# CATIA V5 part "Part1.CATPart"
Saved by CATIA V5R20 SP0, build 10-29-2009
Part number: 底盖
Bounding box of the stored display mesh (mm): x -5 to 4, y -23.984 to 44.814, z -19.949 to 19.949
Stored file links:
  D:\CATIA Data\Part1.CATPart
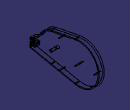
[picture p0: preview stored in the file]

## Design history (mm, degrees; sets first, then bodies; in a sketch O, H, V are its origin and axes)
Body1 (main body)
  Sketch1 on yz-plane, origin (0, 0, 0), H (0, 1, 0), V (0, 0, 1)
    arc A1 centre (0, 0) radius 15 from (-3, 14.6969) to (-12.973, 7.5301) ccw
    arc A2 centre (25, 0) radius 20 from (21, -19.5959) to (21, 19.5959) ccw
    point P1 (25, 0)
    line L1 (21, 19.5959) -> (-3, 14.6969)
    line L2 (21, -19.5959) -> (-3, -14.6969)
    arc A3 centre (-32, 18.5742) radius 22 from (-23.9842, -1.9136) to (-12.973, 7.5301) ccw
    point P6 (-32, 18.5742)
    point P7 (-12.973, 7.5301)
    line L3 (-3, -14.6969) -> (-23.9842, -10.4136)
    line L4 (-23.9842, -10.4136) -> (-23.9842, -1.9136)
    radius A1 = 15
    distance P1 V = 25
    radius A2 = 20
    radius A3 = 22
    distance P6 V = 32
    length L4 = 8.5
    coincidence: P1 H, A3 P7, P7 A1, L3 L2
    tangency: L1 A1, L1 A2, L2 A1, L2 A2, A3 A1, L3 A1
    vertical: L4 V
  Pad1: profile Sketch1, direction (1, 0, 0), length -5
  Shell1: IntOffset 1, Face start face of Pad1, ExtOffset 0
  Sketch2 on face of Shell1, origin (-4, 0, 0), H (0, 1, 0), V (0, 0, 1)
    circle A1 centre (0, 0) radius 1.5
    radius A1 = 1.5
  Pad2: profile Sketch2, direction (1, 0, 0), length 7
  Sketch3 on end face of Pad2, origin (3, 0, 0), H (0, 1, 0), V (0, 0, 1)
    point P1 (0, 0)
  Hole1: placed by Sketch3, at (3, 0, 0) direction (-1, 0, 0), diameter 2, depth 5
  Sketch4 on face of Shell1, origin (-4, 0, 0), H (0, 1, 0), V (0, 0, 1)
    circle A1 centre (25, 0) radius 0.5
    point P1 (25, 0)
    distance P1 V = 25
    radius A1 = 0.5
    coincidence: P1 H
  Pad3: profile Sketch4, direction (1, 0, 0), length 8
  Sketch5 on end face of Pad3, origin (4, 25, 0), H (0, 1, 0), V (0, 0, 1)
    point P1 (0, 0)
  Hole2: placed by Sketch5, at (4, 25, 0) direction (-1, 0, 0), diameter 0.9, depth 7
  Sketch6 on face of Shell1, origin (-4, 0, 0), H (0, 1, 0), V (0, 0, 1)
    axis line L1 (0, 0) -> (13.8636, 27.7272)
    circle A1 centre (6.9318, 13.8636) radius 0.5
    point P2 (6.9318, 13.8636)
    distance O P2 = 15.5
    radius A1 = 0.5
    angle L1 H = 63.4349
    midpoint: P2 L1
  Pad4: profile Sketch6, direction (1, 0, 0), length 6
  Sketch7 on face of Shell1, origin (-4, 0, 0), H (0, 1, 0), V (0, 0, 1)
    axis line L1 (0, 0) -> (20, -40)
    circle A1 centre (6.9318, -13.8636) radius 0.5
    point P2 (6.9318, -13.8636)
    distance O P2 = 15.5
    radius A1 = 0.5
    angle L1 H = 63.4349
    coincidence: P2 L1
  Pad5: profile Sketch7, direction (1, 0, 0), length 6
  Sketch8 on face of Shell1, origin (-4, 0, 0), H (0, 1, 0), V (0, 0, 1)
    circle A1 centre (42, 0) radius 0.5
    point P1 (42, 0)
    distance O P1 = 42
    radius A1 = 0.5
    coincidence: P1 H
  Pad6: profile Sketch8, direction (1, 0, 0), length 6
  Body2
    Sketch9 on face of Pad1 from Sketch1.L4, origin (0, -23.9842, 0), H (1, 0, 0), V (0, 0, 1)
      line L1 (-3, -3.4566) -> (0, -3.4566)
      line L2 (0, -3.4566) -> (0, -8.4566)
      line L3 (0, -8.4566) -> (-3, -8.4566)
      line L4 (-3, -8.4566) -> (-3, -3.4566)
      reference projected line E1 (0, -1.9136) -> (-5, -1.9136) from edge [face of Pad1 from Sketch1.A3 | face of Pad1 from Sketch1.L4]
      reference projected line E2 (0, -1.9136) -> (0, -10.4136) from edge [face of Pad1 from Sketch1.L4 | start face of Pad1]
      length L1 = 3
      length L2 = 5
      distance E1 L1 = 1.543
      horizontal: L1 H, L3 H
      vertical: L2 V, L4 V
      coincidence: L2 E2
    Pad7: profile Sketch9, direction (0, -1, 0), length -1
  Remove1: tool Body2
  Sketch10 on face of Shell1, origin (-4, 0, 0), H (0, 1, 0), V (0, 0, 1)
    line L1 (-22.9842, -4) -> (-17.9842, -4)
    line L2 (-17.9842, -4) -> (-17.9842, -5)
    line L3 (-17.9842, -5) -> (-22.9842, -5)
    line L4 (-22.9842, -5) -> (-22.9842, -4)
    reference projected line E1 (-22.9842, -3.4566) -> (-22.9842, -8.4566) from edge [face of Pad7 from Sketch9.L4 | face of Shell1]
    line L5 (-22.9842, -6) -> (-17.9842, -6)
    line L6 (-17.9842, -6) -> (-17.9842, -7)
    line L7 (-17.9842, -7) -> (-22.9842, -7)
    line L8 (-22.9842, -7) -> (-22.9842, -6)
    reference projected line E2 (-22.9842, -3.4566) -> (-22.9842, -8.4566) from edge [face of Pad7 from Sketch9.L4 | face of Shell1]
    length L1 = 5
    length L4 = 1
    distance H L1 = 4
    length L5 = 5
    length L8 = 1
    distance L5 H = 6
    horizontal: L1 H, L3 H, L5 H, L7 H
    vertical: L2 V, L4 V, L6 V, L8 V
    coincidence: L4 E1, L8 E2
  Pad8: profile Sketch10, direction (1, 0, 0), length 5
  Sketch11 on face of Shell1, origin (-4, 0, 0), H (0, 1, 0), V (0, 0, 1)
    circle A1 centre (-15.5, -5.5) radius 1.25
    point P1 (-15.5, -5.5)
    radius A1 = 1.25
    distance P1 V = 15.5
    distance P1 H = 5.5
  Pad9: profile Sketch11, direction (1, 0, 0), length 7
  Sketch12 on end face of Pad9, origin (3, -15.5, -5.5), H (0, 1, 0), V (0, 0, 1)
    point P1 (0, 0)
  Hole3: placed by Sketch12, at (3, -15.5, -5.5) direction (-1, 0, 0), diameter 2, depth 5
Current feature: Pad8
